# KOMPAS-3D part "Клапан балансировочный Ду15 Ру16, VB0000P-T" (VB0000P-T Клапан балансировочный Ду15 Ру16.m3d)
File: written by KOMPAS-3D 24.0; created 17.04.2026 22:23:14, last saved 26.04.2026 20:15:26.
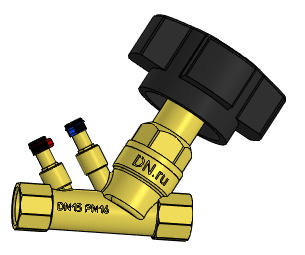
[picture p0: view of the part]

Document properties: Автор: tyuri; Полное имя файла: E:\Работа\Зайцев\АУТСОРС\Диман\Балансировка\VB0000P-T Клапан балансировочный DN.ru Ду15-50 Ру16\DN15\VB0000P-T Клапан балансировочный Ду15 Ру16.m3d

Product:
- Part/product: Клапан балансировочный Ду15 Ру16  | designation VB0000P-T
    Масса: 0.36
    Раздел спецификации: Прочие изделия
    Примечание: D080-01091

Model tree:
1. Операция без истории:3

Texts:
  VB0000P-T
